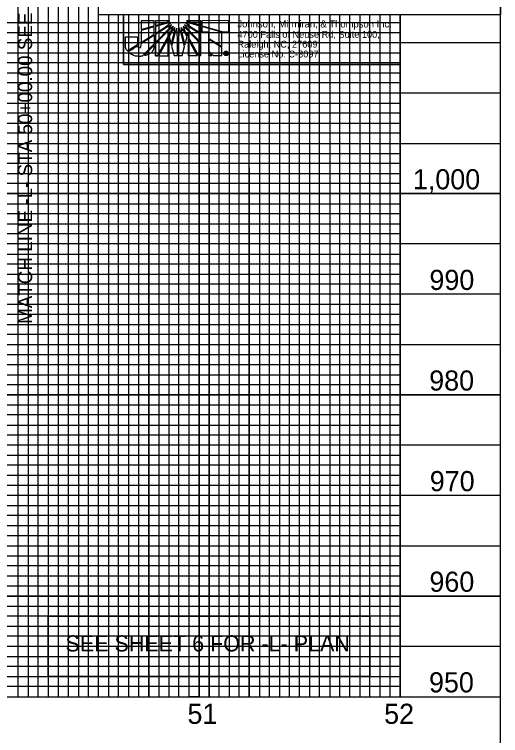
# Model space of a CAD drawing. Extents: x 1626113 to 1628102, y 900759 to 901859.
# Drawn here: x 1627538.1 to 1627779.9, y 901314.9 to 901673.3 of the extents above; entities that cross this region are included whole.
import ezdxf

# ---------------------------------------------------------------- set-up
doc = ezdxf.new("R2010")
doc.units = 0
for name, color, linetype in [('Default', 7, 'Continuous'), ('Matchline Text', 7, 'Continuous'), ('Prop DSN Text', 7, 'Continuous'), ('Prop PHM Black Shape', 7, 'Continuous'), ('Prop Plan Preparation Cover Label', 7, 'Continuous'), ('Sheet DOT Grid CELL', 7, 'Continuous'), ('Sheet Layout Profile Border Port 1', 7, 'Continuous'), ('Sheet Profile CELL', 7, 'Continuous'), ('Sheet Profile Grid Major CELL', 7, 'Continuous'), ('Sheet Profile Grid Middle CELL', 7, 'Continuous'), ('Sheet Sticker Exception Certification CELL', 7, 'Continuous')]:
    doc.layers.add(name, color=color, linetype=linetype)

msp = doc.modelspace()

# ---------------------------------------------------------------- linework, layer by layer
at = {"layer": 'Default'}
for p, q in [((1627607.56, 901670.12), (1627601.13, 901670.12)), ((1627601.13, 901670.12), (1627601.13, 901665.85)), ((1627607.56, 901667.64), (1627607.56, 901670.12)), ((1627615.47, 901670.16), (1627608.23, 901670.15)), ((1627608.23, 901670.15), (1627608.23, 901667.85)), ((1627608.23, 901667.85), (1627613.63, 901669.34)), ((1627613.63, 901668.84), (1627608.23, 901667.35)), ((1627613.07, 901666.93), (1627615.73, 901669.1)), ((1627613.63, 901669.34), (1627615.47, 901670.16)), ((1627615.73, 901669.1), (1627613.63, 901668.84)), ((1627616.26, 901668.1), (1627613.81, 901666.85)), ((1627615.02, 901666.36), (1627616.26, 901668.1)), ((1627622.75, 901668.11), (1627623.99, 901666.33)), ((1627625.24, 901666.86), (1627622.75, 901668.11)), ((1627623.31, 901669.1), (1627626.01, 901666.9)), ((1627625.3, 901668.85), (1627623.31, 901669.1)), ((1627630.81, 901670.14), (1627623.67, 901670.17)), ((1627623.67, 901670.17), (1627625.48, 901669.32)), ((1627630.81, 901667.34), (1627625.3, 901668.85)), ((1627625.48, 901669.32), (1627630.81, 901667.83)), ((1627630.81, 901667.83), (1627630.81, 901670.14)), ((1627644.84, 901670.18), (1627631.31, 901670.17)), ((1627631.31, 901670.17), (1627631.31, 901667.69)), ((1627631.31, 901667.69), (1627631.31, 901667.61)), ((1627644.84, 901664.64), (1627644.84, 901670.18)), ((1627601.13, 901665.85), (1627607.56, 901667.64)), ((1627607.56, 901667.17), (1627601.13, 901665.36)), ((1627601.13, 901665.36), (1627601.13, 901659.36)), ((1627607.57, 901663.44), (1627607.56, 901667.17)), ((1627608.23, 901667.35), (1627608.24, 901663.87)), ((1627608.24, 901663.87), (1627613.07, 901666.93)), ((1627613.81, 901666.85), (1627608.24, 901663.3)), ((1627608.24, 901659.29), (1627615.02, 901666.36)), ((1627615.3, 901666.01), (1627608.24, 901658.61)), ((1627614.87, 901662.81), (1627616.22, 901665.26)), ((1627616.66, 901665.12), (1627615.06, 901662.2)), ((1627617.01, 901667.32), (1627615.3, 901666.01)), ((1627616.09, 901658.34), (1627617.75, 901664.77)), ((1627616.22, 901665.26), (1627617.01, 901667.32)), ((1627618.11, 901664.41), (1627616.3, 901657.45)), ((1627617.93, 901666.75), (1627616.66, 901665.12)), ((1627617.75, 901664.77), (1627617.93, 901666.75)), ((1627618.99, 901666.47), (1627618.11, 901664.41)), ((1627619.27, 901661.39), (1627618.99, 901666.47)), ((1627620.05, 901666.47), (1627619.73, 901661.39)), ((1627620.91, 901664.41), (1627620.05, 901666.47)), ((1627622.76, 901657.35), (1627620.91, 901664.41)), ((1627621.08, 901666.75), (1627621.3, 901664.69)), ((1627622.33, 901665.12), (1627621.08, 901666.75)), ((1627621.3, 901664.69), (1627622.97, 901658.2)), ((1627622, 901667.33), (1627622.78, 901665.27)), ((1627623.71, 901666.01), (1627622, 901667.33)), ((1627624, 901662.11), (1627622.33, 901665.12)), ((1627622.78, 901665.27), (1627624.17, 901662.71)), ((1627630.78, 901658.56), (1627623.71, 901666.01)), ((1627623.99, 901666.33), (1627630.78, 901659.23)), ((1627630.77, 901663.35), (1627625.24, 901666.86)), ((1627626.01, 901666.9), (1627630.77, 901663.93)), ((1627630.77, 901663.93), (1627630.81, 901667.34)), ((1627631.31, 901667.61), (1627641.96, 901664.64)), ((1627631.31, 901667.23), (1627631.31, 901667.19)), ((1627641.29, 901664.39), (1627631.31, 901667.23)), ((1627631.31, 901667.19), (1627631.31, 901664.6)), ((1627631.31, 901664.6), (1627634.62, 901664.6)), ((1627634.62, 901664.6), (1627634.62, 901661.51)), ((1627641.29, 901657.29), (1627641.29, 901664.39)), ((1627641.96, 901664.64), (1627644.84, 901664.64)), ((1627601.13, 901659.36), (1627607.57, 901663.44)), ((1627608.24, 901663.3), (1627608.24, 901659.29)), ((1627609.31, 901652.77), (1627614.56, 901662.28)), ((1627614.56, 901661.35), (1627609.81, 901652.77)), ((1627614.56, 901662.28), (1627614.55, 901663.98)), ((1627614.55, 901663.98), (1627614.87, 901662.81)), ((1627614.61, 901652.77), (1627614.56, 901661.35)), ((1627615.06, 901662.2), (1627616.09, 901658.34)), ((1627619.28, 901652.81), (1627619.27, 901661.39)), ((1627619.73, 901661.39), (1627619.74, 901652.81)), ((1627622.97, 901658.2), (1627624, 901662.11)), ((1627624.17, 901662.71), (1627624.5, 901663.99)), ((1627624.5, 901663.99), (1627624.5, 901662.11)), ((1627624.5, 901662.11), (1627629.64, 901652.79)), ((1627629.11, 901652.82), (1627624.5, 901661.18)), ((1627624.5, 901661.18), (1627624.5, 901652.81)), ((1627630.78, 901659.23), (1627630.77, 901663.35)), ((1627634.62, 901661.51), (1627641.29, 901657.29)), ((1627634.62, 901660.98), (1627634.62, 901655.22)), ((1627641.29, 901656.79), (1627634.62, 901660.98)), ((1627608.24, 901658.61), (1627608.25, 901652.77)), ((1627616.3, 901657.45), (1627617.52, 901652.81)), ((1627621.52, 901652.81), (1627622.76, 901657.35)), ((1627630.78, 901652.79), (1627630.78, 901658.56)), ((1627634.62, 901655.22), (1627636.93, 901652.79)), ((1627636.29, 901652.79), (1627634.62, 901654.6)), ((1627634.62, 901654.6), (1627634.63, 901652.79)), ((1627641.3, 901652.8), (1627641.29, 901656.79)), ((1627642.99, 901653.41), (1627642.99, 901654.39)), ((1627642.99, 901654.39), (1627643.39, 901654.39)), ((1627643.21, 901653.41), (1627642.99, 901653.41)), ((1627643.39, 901654.2), (1627643.21, 901654.2)), ((1627643.21, 901654.2), (1627643.21, 901653.97)), ((1627643.21, 901653.97), (1627643.39, 901653.97)), ((1627643.39, 901653.79), (1627643.21, 901653.79)), ((1627643.21, 901653.79), (1627643.21, 901653.41)), ((1627643.39, 901654.97), (1627643.39, 901654.76)), ((1627643.39, 901654.76), (1627643.39, 901654.97)), ((1627643.39, 901654.39), (1627643.39, 901654.2)), ((1627643.39, 901654.2), (1627643.39, 901654.39)), ((1627643.39, 901654.39), (1627643.45, 901654.39)), ((1627643.42, 901654.2), (1627643.39, 901654.2)), ((1627643.39, 901653.97), (1627643.39, 901653.79)), ((1627643.39, 901653.79), (1627643.39, 901653.97)), ((1627643.39, 901653.97), (1627643.4, 901653.97)), ((1627643.4, 901653.79), (1627643.39, 901653.79)), ((1627608.25, 901652.77), (1627609.31, 901652.77)), ((1627609.81, 901652.77), (1627614.61, 901652.77)), ((1627617.52, 901652.81), (1627619.28, 901652.81)), ((1627619.74, 901652.81), (1627621.52, 901652.81)), ((1627624.5, 901652.81), (1627629.11, 901652.82)), ((1627629.64, 901652.79), (1627630.78, 901652.79)), ((1627634.63, 901652.79), (1627636.29, 901652.79)), ((1627636.93, 901652.79), (1627641.3, 901652.8)), ((1627643.39, 901653.02), (1627643.39, 901652.81)), ((1627643.39, 901652.81), (1627643.39, 901653.02)), ((1627643.39, 901653.02), (1627643.4, 901653.02)), ((1627643.4, 901652.81), (1627643.39, 901652.81))]:
    msp.add_line(p, q, dxfattribs=at)
for points in [[(1627592.42, 901648.34), (1627729.94, 901648.33), (1627729.95, 901673.15), (1627592.42, 901673.16)], [(1627623.67, 901670.17), (1627630.81, 901670.14), (1627630.81, 901667.83), (1627625.48, 901669.32)], [(1627608.25, 901652.77), (1627608.24, 901658.61), (1627615.3, 901666.01), (1627617.01, 901667.32), (1627616.44, 901665.7), (1627614.87, 901662.81), (1627614.55, 901663.98), (1627614.56, 901662.28), (1627609.31, 901652.77)]]:
    msp.add_lwpolyline(points, close=True, dxfattribs=at)
for points in [[(1627601.13, 901665.85), (1627607.56, 901667.64), (1627607.56, 901670.12), (1627601.13, 901670.12), (1627601.13, 901665.85)], [(1627613.63, 901669.34), (1627615.47, 901670.16), (1627608.23, 901670.15), (1627608.23, 901667.85), (1627613.63, 901669.34)], [(1627608.23, 901667.35), (1627608.24, 901663.87), (1627613.07, 901666.93), (1627615.73, 901669.1), (1627613.63, 901668.84), (1627608.23, 901667.35)], [(1627608.24, 901663.3), (1627608.24, 901659.29), (1627615.02, 901666.36), (1627616.26, 901668.1), (1627613.81, 901666.85), (1627608.24, 901663.3)], [(1627622.75, 901668.11), (1627623.99, 901666.33), (1627630.78, 901659.23), (1627630.77, 901663.35), (1627625.24, 901666.86), (1627622.75, 901668.11)], [(1627623.31, 901669.1), (1627626.01, 901666.9), (1627630.77, 901663.93), (1627630.81, 901667.34), (1627625.3, 901668.85), (1627623.31, 901669.1)], [(1627625.48, 901669.32), (1627630.81, 901667.83), (1627630.81, 901670.14), (1627623.67, 901670.17), (1627625.48, 901669.32)], [(1627644.84, 901670.18), (1627631.31, 901670.17), (1627631.31, 901667.69), (1627631.31, 901667.61), (1627641.96, 901664.64), (1627644.84, 901664.64), (1627644.84, 901670.18)], [(1627601.13, 901659.36), (1627607.57, 901663.44), (1627607.56, 901667.17), (1627601.13, 901665.36), (1627601.13, 901659.36)], [(1627617.01, 901667.32), (1627615.3, 901666.01), (1627608.24, 901658.61), (1627608.25, 901652.77), (1627609.31, 901652.77), (1627614.56, 901662.28), (1627614.55, 901663.98), (1627614.87, 901662.81), (1627616.22, 901665.26), (1627617.01, 901667.32)], [(1627617.93, 901666.75), (1627616.66, 901665.12), (1627615.06, 901662.2), (1627616.09, 901658.34), (1627617.75, 901664.77), (1627617.93, 901666.75)], [(1627618.11, 901664.41), (1627616.3, 901657.45), (1627617.52, 901652.81), (1627619.28, 901652.81), (1627619.27, 901661.39), (1627618.99, 901666.47), (1627618.11, 901664.41)], [(1627620.05, 901666.47), (1627619.73, 901661.39), (1627619.74, 901652.81), (1627621.52, 901652.81), (1627622.76, 901657.35), (1627620.91, 901664.41), (1627620.05, 901666.47)], [(1627621.08, 901666.75), (1627621.3, 901664.69), (1627622.97, 901658.2), (1627624, 901662.11), (1627622.33, 901665.12), (1627621.08, 901666.75)], [(1627622, 901667.33), (1627622.78, 901665.27), (1627624.17, 901662.71), (1627624.5, 901663.99), (1627624.5, 901662.11), (1627629.64, 901652.79), (1627630.78, 901652.79), (1627630.78, 901658.56), (1627623.71, 901666.01), (1627622, 901667.33)], [(1627631.31, 901667.23), (1627631.31, 901667.19), (1627631.31, 901664.6), (1627634.62, 901664.6), (1627634.62, 901661.51), (1627641.29, 901657.29), (1627641.29, 901664.39), (1627631.31, 901667.23)], [(1627609.81, 901652.77), (1627614.61, 901652.77), (1627614.56, 901661.35), (1627609.81, 901652.77)], [(1627624.5, 901652.81), (1627629.11, 901652.82), (1627624.5, 901661.18), (1627624.5, 901652.81)], [(1627634.62, 901660.98), (1627634.62, 901655.22), (1627636.93, 901652.79), (1627641.3, 901652.8), (1627641.29, 901656.79), (1627634.62, 901660.98), (1627634.62, 901660.98)], [(1627634.63, 901652.79), (1627634.63, 901652.79), (1627636.29, 901652.79), (1627634.62, 901654.6), (1627634.63, 901652.79)], [(1627643.82, 901653.64), (1627643.82, 901653.58), (1627643.83, 901653.55), (1627643.83, 901653.51), (1627643.86, 901653.41), (1627643.65, 901653.41)]]:
    msp.add_lwpolyline(points, dxfattribs=at)
for points, degree in [([(1627599.28, 901662.12), (1627599.28, 901662.12), (1627593.33, 901662.11), (1627593.33, 901662.11), (1627593.33, 901662.11), (1627593.33, 901658.38), (1627593.33, 901658.38), (1627593.33, 901658.38), (1627593.33, 901657.99), (1627593.33, 901657.99), (1627593.33, 901656.82), (1627593.71, 901655.9), (1627594.39, 901655.12), (1627594.39, 901655.12), (1627599.29, 901658.1), (1627599.29, 901658.18), (1627599.29, 901658.18), (1627599.28, 901662.12), (1627599.28, 901662.12)], 3), ([(1627600.21, 901656.75), (1627599.83, 901656.75), (1627599.5, 901656.97), (1627599.36, 901657.68), (1627599.36, 901657.68), (1627594.75, 901654.82), (1627594.75, 901654.82), (1627596.17, 901653.32), (1627598.44, 901652.43), (1627600.37, 901652.43), (1627600.86, 901652.43), (1627601.25, 901652.47), (1627601.78, 901652.58), (1627601.78, 901652.58), (1627607.57, 901658.58), (1627607.57, 901658.58), (1627607.57, 901658.58), (1627607.57, 901662.91), (1627607.57, 901662.91), (1627607.57, 901662.91), (1627601.14, 901658.82), (1627601.14, 901658.82), (1627601.14, 901657.19), (1627600.74, 901656.75), (1627600.21, 901656.75)], 3), ([(1627600.21, 901656.75), (1627599.83, 901656.75), (1627599.5, 901656.97), (1627599.36, 901657.68), (1627599.36, 901657.68), (1627594.75, 901654.82), (1627594.75, 901654.82), (1627596.17, 901653.32), (1627598.44, 901652.43), (1627600.37, 901652.43), (1627600.86, 901652.43), (1627601.25, 901652.47), (1627601.78, 901652.58), (1627601.78, 901652.58), (1627607.57, 901658.58), (1627607.57, 901658.58), (1627607.57, 901658.58), (1627607.57, 901662.91), (1627607.57, 901662.91), (1627607.57, 901662.91), (1627601.14, 901658.82), (1627601.14, 901658.82), (1627601.14, 901657.19), (1627600.74, 901656.75), (1627600.21, 901656.75)], 3), ([(1627607.57, 901657.9), (1627607.57, 901657.9), (1627602.56, 901652.72), (1627602.56, 901652.72), (1627605.02, 901653.33), (1627607.46, 901654.95), (1627607.57, 901657.9)], 3), ([(1627643.39, 901652.81), (1627643.1, 901652.81), (1627642.84, 901652.91), (1627642.62, 901653.13), (1627642.41, 901653.33), (1627642.3, 901653.59), (1627642.3, 901653.9), (1627642.3, 901654.2), (1627642.41, 901654.46), (1627642.62, 901654.66), (1627642.84, 901654.86), (1627643.09, 901654.97), (1627643.39, 901654.97)], 3), ([(1627643.39, 901654.76), (1627643.15, 901654.76), (1627642.94, 901654.68), (1627642.77, 901654.52), (1627642.6, 901654.35), (1627642.51, 901654.14), (1627642.51, 901653.9), (1627642.52, 901653.66), (1627642.6, 901653.44), (1627642.77, 901653.27), (1627642.95, 901653.1), (1627643.15, 901653.02), (1627643.39, 901653.02)], 3), ([(1627643.39, 901654.97), (1627643.69, 901654.97), (1627643.95, 901654.86), (1627644.17, 901654.66), (1627644.38, 901654.46), (1627644.49, 901654.2), (1627644.49, 901653.9)], 3), ([(1627643.4, 901653.02), (1627643.64, 901653.02), (1627643.85, 901653.1), (1627644.02, 901653.27), (1627644.19, 901653.44), (1627644.28, 901653.66), (1627644.28, 901653.9), (1627644.28, 901654.14), (1627644.19, 901654.35), (1627644.02, 901654.52), (1627643.85, 901654.68), (1627643.64, 901654.77), (1627643.39, 901654.76)], 3), ([(1627643.4, 901653.97), (1627643.54, 901653.97), (1627643.61, 901654.01), (1627643.61, 901654.09), (1627643.61, 901654.17), (1627643.55, 901654.2), (1627643.42, 901654.2)], 3), ([(1627644.49, 901653.9), (1627644.49, 901653.59), (1627644.38, 901653.33), (1627644.18, 901653.12), (1627643.96, 901652.91), (1627643.71, 901652.81), (1627643.4, 901652.81)], 3), ([(1627643.57, 901653.75), (1627643.54, 901653.77), (1627643.49, 901653.79), (1627643.4, 901653.79)], 2), ([(1627643.45, 901654.39), (1627643.7, 901654.39), (1627643.83, 901654.29), (1627643.83, 901654.09), (1627643.83, 901654.01), (1627643.79, 901653.93), (1627643.71, 901653.88)], 3), ([(1627643.65, 901653.41), (1627643.62, 901653.46), (1627643.61, 901653.51), (1627643.61, 901653.58), (1627643.61, 901653.67), (1627643.6, 901653.73), (1627643.57, 901653.75)], 3), ([(1627643.71, 901653.88), (1627643.78, 901653.84), (1627643.81, 901653.76), (1627643.82, 901653.64)], 2)]:
    msp.add_open_spline(points, degree=degree, dxfattribs=at)
at = {"layer": 'Prop DSN Text'}
msp.add_lwpolyline([(1627554.95, 901374.2), (1627714.95, 901374.2), (1627714.95, 901344.2), (1627554.95, 901344.2)], close=True, dxfattribs=at)
at = {"layer": 'Prop PHM Black Shape'}
for points in [[(1627592.42, 901673.16), (1627729.94, 901673.16), (1627729.94, 901648.33), (1627592.42, 901648.33)], [(1627554.95, 901374.2), (1627714.95, 901374.2), (1627714.95, 901344.2), (1627554.95, 901344.2)]]:
    msp.add_lwpolyline(points, close=True, dxfattribs=at)
at = {"layer": 'Prop Plan Preparation Cover Label'}
for p, q in [((1626329.95, 901669.2), (1627729.95, 901669.2)), ((1627729.95, 901649.2), (1626329.95, 901649.2)), ((1626329.95, 901644.2), (1627729.95, 901644.2)), ((1627729.95, 901624.2), (1626329.95, 901624.2)), ((1626329.95, 901619.2), (1627729.95, 901619.2)), ((1627729.95, 901599.2), (1626329.95, 901599.2)), ((1626329.95, 901594.2), (1627729.95, 901594.2)), ((1627729.95, 901589.2), (1626329.95, 901589.2)), ((1626329.95, 901579.2), (1627729.95, 901579.2)), ((1627729.95, 901574.2), (1626329.95, 901574.2)), ((1626329.95, 901569.2), (1627729.95, 901569.2)), ((1627729.95, 901564.2), (1626329.95, 901564.2)), ((1626329.95, 901554.2), (1627729.95, 901554.2)), ((1627729.95, 901549.2), (1626329.95, 901549.2)), ((1626329.95, 901544.2), (1627729.95, 901544.2)), ((1627729.95, 901539.2), (1626329.95, 901539.2)), ((1626329.95, 901529.2), (1627729.95, 901529.2)), ((1627729.95, 901524.2), (1626329.95, 901524.2)), ((1626329.95, 901519.2), (1627729.95, 901519.2)), ((1627729.95, 901514.2), (1626329.95, 901514.2)), ((1626329.95, 901504.2), (1627729.95, 901504.2)), ((1627729.95, 901499.2), (1626329.95, 901499.2)), ((1626329.95, 901494.2), (1627729.95, 901494.2)), ((1627729.95, 901489.2), (1626329.95, 901489.2)), ((1626329.95, 901479.2), (1627729.95, 901479.2)), ((1627729.95, 901474.2), (1626329.95, 901474.2)), ((1626329.95, 901469.2), (1627729.95, 901469.2)), ((1627729.95, 901464.2), (1626329.95, 901464.2)), ((1626329.95, 901454.2), (1627729.95, 901454.2)), ((1627729.95, 901449.2), (1626329.95, 901449.2)), ((1627729.95, 901444.2), (1626329.95, 901444.2)), ((1627729.95, 901439.2), (1626329.95, 901439.2)), ((1626329.95, 901429.2), (1627729.95, 901429.2)), ((1627729.95, 901424.2), (1626329.95, 901424.2)), ((1626329.95, 901419.2), (1627729.95, 901419.2)), ((1627729.95, 901414.2), (1626329.95, 901414.2)), ((1626329.95, 901404.2), (1627729.95, 901404.2)), ((1627729.95, 901399.2), (1626329.95, 901399.2)), ((1626329.95, 901394.2), (1627729.95, 901394.2)), ((1627729.95, 901389.2), (1626329.95, 901389.2)), ((1626329.95, 901379.2), (1627729.95, 901379.2)), ((1627729.95, 901374.2), (1626329.95, 901374.2)), ((1626329.95, 901369.2), (1627729.95, 901369.2)), ((1627729.95, 901364.2), (1626329.95, 901364.2)), ((1626329.95, 901354.2), (1627729.95, 901354.2)), ((1627729.95, 901349.2), (1626329.95, 901349.2)), ((1626329.95, 901344.2), (1627729.95, 901344.2))]:
    msp.add_line(p, q, dxfattribs=at)
for points in [[(1627534.95, 901334.2), (1627539.95, 901334.2), (1627539.95, 901834.2), (1627544.95, 901834.2), (1627544.95, 901334.2), (1627549.95, 901334.2), (1627549.95, 901834.2), (1627559.95, 901834.2), (1627559.95, 901334.2), (1627564.95, 901334.2), (1627564.95, 901834.2), (1627569.95, 901834.2), (1627569.95, 901334.2), (1627574.95, 901334.2), (1627574.95, 901834.2), (1627584.95, 901834.2)], [(1627584.95, 901673.15), (1627584.95, 901334.2), (1627589.95, 901334.2), (1627589.95, 901673.15)], [(1627594.95, 901673.15), (1627594.95, 901334.2), (1627599.95, 901334.2), (1627599.95, 901673.15)], [(1627609.95, 901673.15), (1627609.95, 901334.2), (1627609.95, 901334.2), (1627614.95, 901334.2), (1627619.95, 901334.2), (1627619.95, 901673.15)], [(1627614.95, 901673.15), (1627614.95, 901334.2)], [(1627624.94, 901673.15), (1627624.85, 901334.25), (1627629.85, 901334.25), (1627634.95, 901334.2), (1627634.95, 901673.15)], [(1627634.95, 901597), (1627634.95, 901334.2), (1627639.95, 901334.2), (1627639.95, 901673.15)], [(1627644.95, 901673.15), (1627644.95, 901334.2), (1627649.95, 901334.2), (1627649.95, 901673.15)], [(1627659.95, 901673.15), (1627659.95, 901334.2), (1627664.95, 901334.2), (1627664.95, 901673.15)], [(1627669.95, 901673.15), (1627669.95, 901334.2), (1627674.95, 901334.2), (1627674.95, 901673.15)], [(1627684.95, 901673.15), (1627684.95, 901334.2), (1627689.95, 901334.2), (1627689.95, 901673.15)], [(1627694.95, 901673.15), (1627694.95, 901334.2), (1627699.95, 901334.2), (1627699.95, 901673.15)], [(1627709.95, 901673.15), (1627709.95, 901334.2), (1627714.95, 901334.2), (1627714.95, 901673.15)], [(1627719.95, 901673.15), (1627719.95, 901334.2), (1627724.95, 901334.2), (1627724.95, 901673.15)], [(1627729.95, 901664.2), (1626329.95, 901664.2), (1626329.95, 901654.2), (1627729.95, 901654.2)], [(1627729.95, 901639.2), (1626329.95, 901639.2), (1626329.95, 901629.2), (1627729.95, 901629.2)], [(1627729.95, 901614.2), (1626329.95, 901614.2), (1626329.95, 901604.2), (1627729.95, 901604.2)], [(1627729.95, 901339.2), (1626329.95, 901339.2)]]:
    msp.add_lwpolyline(points, dxfattribs=at)
at = {"layer": 'Sheet DOT Grid CELL'}
for p, q in [((1627579.95, 901334.2), (1627579.95, 901696.65)), ((1627629.95, 901334.2), (1627629.95, 901673.15)), ((1627679.95, 901334.2), (1627679.95, 901673.15)), ((1627729.95, 901334.2), (1627729.95, 901673.15)), ((1627779.95, 901634.2), (1626279.95, 901634.2)), ((1627779.95, 901584.2), (1626279.95, 901584.2)), ((1627779.95, 901534.2), (1626279.95, 901534.2)), ((1627779.95, 901484.2), (1626279.95, 901484.2)), ((1627779.95, 901434.2), (1626279.95, 901434.2)), ((1627779.95, 901384.2), (1626279.95, 901384.2))]:
    msp.add_line(p, q, dxfattribs=at)
at = {"layer": 'Sheet Layout Profile Border Port 1'}
msp.add_lwpolyline([(1626329.95, 901673.15), (1626329.95, 901334.2), (1627729.95, 901334.2), (1627729.95, 901673.15)], dxfattribs=at)
at = {"layer": 'Sheet Profile CELL'}
msp.add_line((1626279.95, 901334.2), (1627779.95, 901334.2), dxfattribs=at)
msp.add_lwpolyline([(1627779.95, 901834.2), (1626279.95, 901834.2), (1626279.95, 900784.2), (1627779.95, 900784.2)], close=True, dxfattribs=at)
at = {"layer": 'Sheet Profile Grid Major CELL'}
for points in [[(1627129.95, 901334.2), (1627179.95, 901334.2), (1627179.95, 901834.2), (1627229.95, 901834.2), (1627229.95, 901334.2), (1627279.95, 901334.2), (1627279.95, 901834.2), (1627329.95, 901834.2), (1627329.95, 901334.2), (1627379.95, 901334.2), (1627379.95, 901834.2), (1627429.95, 901834.2), (1627429.95, 901334.2), (1627479.95, 901334.2), (1627479.95, 901834.2), (1627529.95, 901834.2), (1627529.95, 901334.2), (1627579.95, 901334.2), (1627579.95, 901834.2), (1627606.25, 901834.2)], [(1627729.95, 901673.15), (1627729.95, 901334.2), (1627779.95, 901334.2), (1627779.95, 901684.2)], [(1627629.95, 901673.15), (1627629.95, 901334.2), (1627679.95, 901334.2), (1627679.95, 901334.2), (1627679.95, 901673.15)], [(1627779.95, 901634.2), (1626279.95, 901634.2), (1626279.95, 901584.2), (1627779.95, 901584.2)], [(1627779.95, 901534.2), (1626279.95, 901534.2), (1626279.95, 901484.2), (1627779.95, 901484.2)], [(1627779.95, 901434.2), (1626279.95, 901434.2), (1626279.95, 901434.2), (1626279.95, 901384.2), (1627779.95, 901384.2)]]:
    msp.add_lwpolyline(points, dxfattribs=at)
at = {"layer": 'Sheet Profile Grid Middle CELL'}
for points in [[(1627104.95, 901834.2), (1627154.95, 901834.2), (1627154.95, 901334.2), (1627204.95, 901334.2), (1627204.95, 901834.2), (1627254.95, 901834.2), (1627254.95, 901334.2), (1627304.95, 901334.2), (1627304.95, 901834.2), (1627354.95, 901834.2), (1627354.95, 901334.2), (1627404.95, 901334.2), (1627404.95, 901834.2), (1627454.95, 901834.2), (1627454.95, 901334.2), (1627504.95, 901334.2), (1627504.95, 901834.2), (1627554.95, 901834.2), (1627554.95, 901334.2), (1627604.95, 901334.2), (1627604.95, 901673.15)], [(1627604.95, 901597), (1627604.95, 901334.2), (1627654.95, 901334.2), (1627654.95, 901673.15)], [(1627654.95, 901597), (1627654.95, 901334.2), (1627704.95, 901334.2), (1627704.95, 901673.15)], [(1627779.95, 901659.2), (1626279.95, 901659.2), (1626279.95, 901609.2), (1627604.95, 901609.2)], [(1627604.95, 901609.2), (1627779.95, 901609.2)], [(1627779.95, 901559.2), (1626279.95, 901559.2), (1626279.95, 901509.2), (1627779.95, 901509.2)], [(1627779.95, 901459.2), (1626279.95, 901459.2), (1626279.95, 901409.2), (1627779.95, 901409.2)], [(1627779.95, 901359.2), (1626279.95, 901359.2)]]:
    msp.add_lwpolyline(points, dxfattribs=at)
at = {"layer": 'Sheet Sticker Exception Certification CELL'}
for p, q in [((1627579.9, 901673.15), (1627579.9, 901696.65)), ((1627579.9, 901673.15), (1627579.9, 901696.65)), ((1627779.93, 901696.64), (1627779.93, 901673.14)), ((1627779.93, 901696.64), (1627779.93, 901673.14)), ((1627779.93, 901673.15), (1627579.9, 901673.15)), ((1627779.93, 901673.15), (1627579.9, 901673.15))]:
    msp.add_line(p, q, dxfattribs=at)

# ---------------------------------------------------------------- texts
at = {"layer": 'Default'}
for s, height, p in [('Johnson, Mirmiran, & Thompson Inc.', 3.5139, (1627649.06, 901666.8)), ('4700 Falls of Neuse Rd, Suite 100, ', 3.4135, (1627649.06, 901661.64)), ('Raleigh, NC, 27609', 3.4135, (1627649.06, 901656.77)), ('License No: C-3097', 3.4135, (1627649.06, 901651.89))]:
    msp.add_text(s, height=height, rotation=359.9946, dxfattribs=at).set_placement(p)
for s, p in [('1,000', (1627736.33, 901586.34)), ('990', (1627744.56, 901536.34)), ('980', (1627744.45, 901486.34)), ('970', (1627744.73, 901436.34)), ('960', (1627744.56, 901386.34)), ('950', (1627744.34, 901336.34)), ('52', (1627722.03, 901320.7)), ('51', (1627624.2, 901320.7))]:
    msp.add_text(s, height=10, dxfattribs=at).set_placement(p)
at = {"layer": 'Matchline Text'}
msp.add_text('MATCH LINE -L- STA 50+00.00 SEE BELOW', height=7, rotation=90, dxfattribs=at).set_placement((1627546.95, 901519.45))
at = {"layer": 'Prop DSN Text'}
msp.add_text('SEE SHEET 6 FOR -L- PLAN', height=8, dxfattribs=at).set_placement((1627563.52, 901356.69))

doc.saveas('drawing.dxf')
